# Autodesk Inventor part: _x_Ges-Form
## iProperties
Created: 2005-11
Part Number: _x_Ges-Form
Document SubType Name: Modeling
Designer: IMA/Frank
Manufacturer: Standard
Standards Organization: Custom
Author: IMA/Frank
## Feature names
1. Extrusion1
